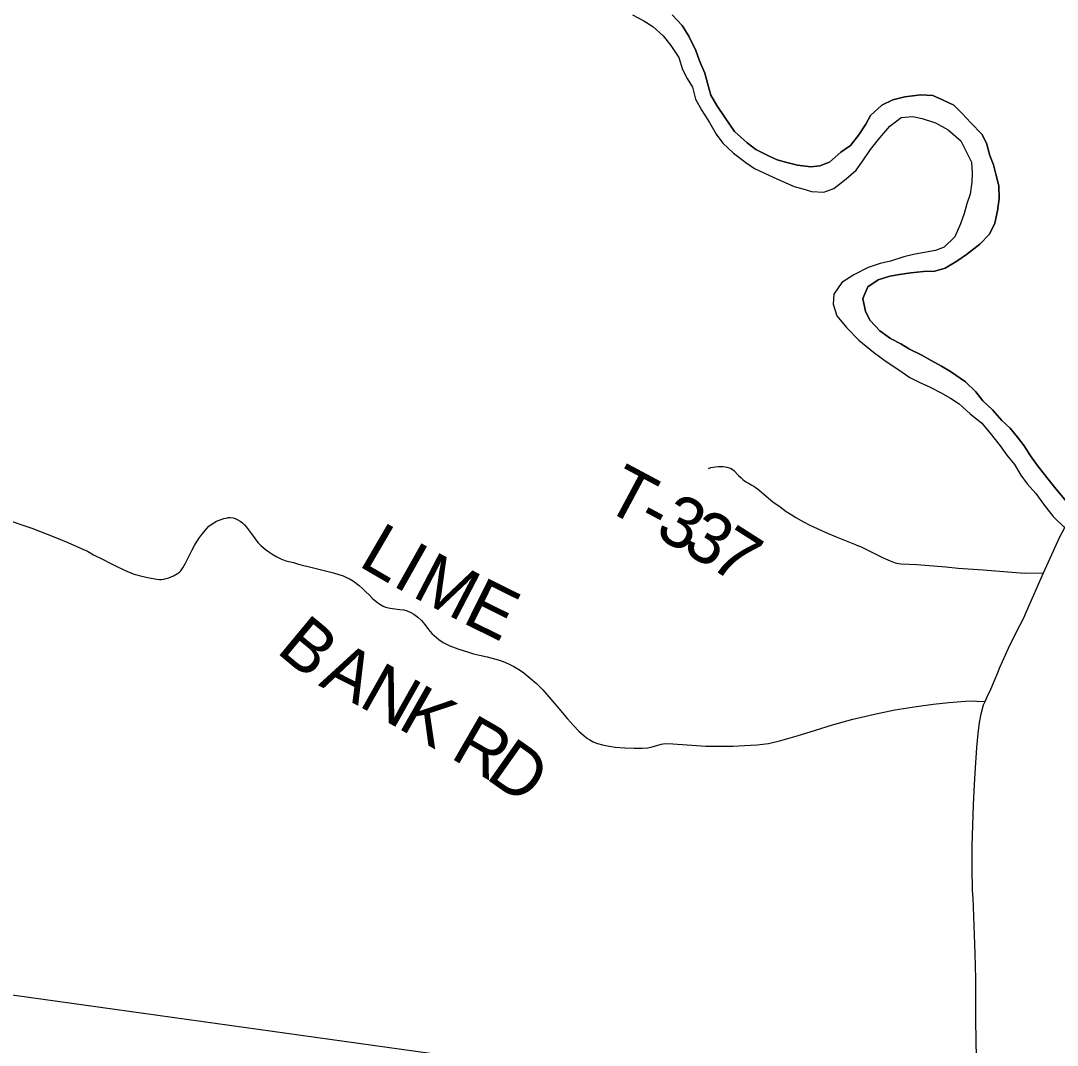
# Model space of a CAD drawing. Extents: x 0 to 34, y 0 to 22.
# Drawn here: x 6.535 to 7.688, y 17.181 to 18.32 of the extents above; entities that cross this region are included whole.
import ezdxf

# ---------------------------------------------------------------- set-up
doc = ezdxf.new("R2010")
doc.units = 0
for name, color, linetype in [('GM_X_County_Road', 7, 'Continuous'), ('GM_X_County_Road_Text', 7, 'Continuous'), ('GM_X_Major_River', 7, 'Continuous'), ('GM_X_Township_Road', 7, 'Continuous'), ('GM_X_Township_Road_Text', 7, 'Continuous'), ('SH_Text', 7, 'Continuous')]:
    doc.layers.add(name, color=color, linetype=linetype)

msp = doc.modelspace()

# ---------------------------------------------------------------- linework, layer by layer
at = {"layer": 'GM_X_County_Road'}
for points in [[(7.6778, 17.7185), (7.6905, 17.7463), (7.7139, 17.7898), (7.7207, 17.8036), (7.7258, 17.8149), (7.7303, 17.8264), (7.7343, 17.8381), (7.7388, 17.8529), (7.7434, 17.8694), (7.7504, 17.8946)], [(6.5182, 17.7655), (6.5469, 17.7559), (6.5725, 17.746), (6.587, 17.7401), (6.6011, 17.7339), (6.6087, 17.7303), (6.6156, 17.7265), (6.6262, 17.7212), (6.6334, 17.7173), (6.6393, 17.7144), (6.65, 17.7094), (6.6597, 17.7054), (6.6649, 17.7037), (6.6754, 17.701), (6.6818, 17.6999), (6.6861, 17.6993), (6.6889, 17.6991), (6.691, 17.6991), (6.6937, 17.6994), (6.6965, 17.7), (6.6993, 17.7008), (6.702, 17.7018), (6.7045, 17.7029), (6.7091, 17.7055), (6.7112, 17.7071), (6.7127, 17.7085), (6.715, 17.7118), (6.718, 17.7172), (6.7248, 17.7313), (6.7277, 17.7368), (6.7326, 17.7444), (6.7359, 17.7488), (6.7439, 17.7583), (6.7464, 17.7602), (6.7493, 17.7621), (6.7522, 17.7637), (6.7552, 17.7649), (6.7575, 17.7656), (6.7605, 17.7667), (6.7631, 17.7673), (6.7655, 17.7677), (6.7676, 17.7679), (6.7707, 17.7674), (6.7732, 17.7666), (6.7759, 17.7654), (6.7787, 17.7639), (6.7812, 17.7619), (6.7835, 17.7597), (6.7856, 17.7573), (6.7912, 17.7498), (6.7954, 17.744), (6.7984, 17.7401), (6.8018, 17.7366), (6.8064, 17.7326), (6.8107, 17.7296), (6.8151, 17.7267), (6.8195, 17.724), (6.824, 17.7218), (6.8296, 17.7198), (6.8378, 17.7177), (6.8435, 17.716), (6.849, 17.7145), (6.8544, 17.7132), (6.8602, 17.7119), (6.8825, 17.7062), (6.8931, 17.703), (6.8956, 17.702), (6.9011, 17.6994), (6.9046, 17.697), (6.9111, 17.6921), (6.9152, 17.6884), (6.9181, 17.6856), (6.9225, 17.6814), (6.926, 17.6779), (6.9299, 17.6743), (6.9339, 17.6715), (6.9377, 17.6693), (6.9402, 17.6682), (6.9454, 17.667), (6.9507, 17.6662), (6.9562, 17.6656), (6.9607, 17.665), (6.9645, 17.6639), (6.9686, 17.6623), (6.9719, 17.6603), (6.9764, 17.657), (6.9804, 17.6532), (6.9839, 17.6489), (6.9882, 17.6432), (6.992, 17.6387), (6.9996, 17.6322), (7.0045, 17.6288), (7.0119, 17.6253), (7.0207, 17.6219), (7.0326, 17.6182), (7.0383, 17.6164), (7.0449, 17.6149), (7.0536, 17.6129), (7.0655, 17.6095), (7.0713, 17.6076), (7.077, 17.6052), (7.0832, 17.6021), (7.0895, 17.5983), (7.0941, 17.595), (7.1014, 17.5893), (7.1082, 17.5833), (7.1154, 17.5762), (7.1332, 17.5553), (7.1427, 17.544), (7.1495, 17.5364), (7.1554, 17.5303), (7.1612, 17.5251), (7.1649, 17.5222), (7.1675, 17.5207), (7.1712, 17.5185), (7.1762, 17.5165), (7.1819, 17.515), (7.1874, 17.5139), (7.1957, 17.5125), (7.2065, 17.5116), (7.217, 17.5112), (7.2257, 17.5113), (7.232, 17.5118), (7.237, 17.5127), (7.2408, 17.5138), (7.2448, 17.5151), (7.247, 17.5157), (7.2491, 17.5162), (7.2515, 17.5164), (7.2601, 17.5162), (7.2759, 17.5151), (7.2968, 17.5136), (7.3123, 17.5134), (7.327, 17.5136), (7.3398, 17.5142), (7.3465, 17.5145), (7.3538, 17.515), (7.3663, 17.5165), (7.3803, 17.52), (7.3984, 17.5251), (7.4186, 17.5313), (7.4376, 17.5373), (7.4601, 17.5435), (7.4842, 17.5492), (7.507, 17.5538), (7.531, 17.5576), (7.5494, 17.5603), (7.5671, 17.5621), (7.5857, 17.5636), (7.5951, 17.5638), (7.5982, 17.5637), (7.6073, 17.5633)], [(7.6073, 17.5633), (7.6095, 17.5685), (7.6136, 17.5771), (7.6218, 17.5964), (7.6233, 17.6003), (7.6334, 17.6224), (7.6417, 17.6394), (7.6504, 17.6563), (7.6535, 17.6632), (7.6724, 17.7063), (7.6778, 17.7185)], [(7.5978, 17.1626), (7.5975, 17.191), (7.5971, 17.2049), (7.5969, 17.2385), (7.5969, 17.2549), (7.5964, 17.283), (7.5943, 17.3348), (7.5939, 17.3447), (7.5934, 17.3532), (7.5928, 17.3779), (7.5931, 17.4029), (7.5944, 17.4484), (7.5957, 17.4709), (7.5963, 17.4837), (7.5982, 17.5122), (7.5996, 17.5277), (7.6013, 17.54), (7.6031, 17.5497), (7.6056, 17.5595), (7.6073, 17.5633)]]:
    msp.add_lwpolyline(points, dxfattribs=at)
at = {"layer": 'GM_X_Major_River'}
for p, q in [((7.2152, 18.3269), (7.2277, 18.3202)), ((7.2702, 18.3149), (7.2591, 18.3269)), ((7.2277, 18.3202), (7.2376, 18.3139)), ((7.2376, 18.3139), (7.2494, 18.3037)), ((7.2778, 18.3032), (7.2702, 18.3149)), ((7.2494, 18.3037), (7.2579, 18.2928)), ((7.2855, 18.2874), (7.2778, 18.3032)), ((7.2579, 18.2928), (7.2667, 18.2796)), ((7.2667, 18.2796), (7.2706, 18.266)), ((7.2898, 18.2757), (7.2855, 18.2874)), ((7.2706, 18.266), (7.276, 18.2562)), ((7.2956, 18.2621), (7.2898, 18.2757)), ((7.276, 18.2562), (7.2817, 18.2464)), ((7.2987, 18.2508), (7.2956, 18.2621)), ((7.2817, 18.2464), (7.2852, 18.2332)), ((7.3022, 18.2375), (7.2987, 18.2508)), ((7.2852, 18.2332), (7.2922, 18.2204)), ((7.3091, 18.2262), (7.3022, 18.2375)), ((7.5047, 18.2325), (7.4923, 18.2264)), ((7.5179, 18.2357), (7.5047, 18.2325)), ((7.5357, 18.2378), (7.5179, 18.2357)), ((7.5493, 18.2371), (7.5357, 18.2378)), ((7.56, 18.2323), (7.5493, 18.2371)), ((7.5725, 18.2263), (7.56, 18.2323)), ((7.2922, 18.2204), (7.3006, 18.2072)), ((7.3183, 18.2123), (7.3091, 18.2262)), ((7.4923, 18.2264), (7.4799, 18.2149)), ((7.582, 18.217), (7.5725, 18.2263)), ((7.3287, 18.1972), (7.3183, 18.2123)), ((7.4799, 18.2149), (7.4747, 18.2054)), ((7.5012, 18.203), (7.514, 18.2129)), ((7.514, 18.2129), (7.5268, 18.2138)), ((7.5268, 18.2138), (7.5374, 18.2116)), ((7.5374, 18.2116), (7.5522, 18.2068)), ((7.5916, 18.2068), (7.582, 18.217)), ((7.3006, 18.2072), (7.3083, 18.194)), ((7.3428, 18.1845), (7.3287, 18.1972)), ((7.4747, 18.2054), (7.4668, 18.1935)), ((7.4903, 18.19), (7.5012, 18.203)), ((7.5522, 18.2068), (7.5663, 18.199)), ((7.5663, 18.199), (7.5804, 18.1866)), ((7.6038, 18.194), (7.5916, 18.2068)), ((7.3083, 18.194), (7.3156, 18.1842)), ((7.3523, 18.1773), (7.3428, 18.1845)), ((7.4668, 18.1935), (7.4575, 18.1817)), ((7.4798, 18.177), (7.4903, 18.19)), ((7.5804, 18.1866), (7.5923, 18.1632)), ((7.6088, 18.1842), (7.6038, 18.194)), ((7.6127, 18.1706), (7.6088, 18.1842)), ((7.3156, 18.1842), (7.3274, 18.173)), ((7.3274, 18.173), (7.3411, 18.1625)), ((7.3664, 18.1699), (7.3523, 18.1773)), ((7.447, 18.174), (7.4342, 18.1629)), ((7.4575, 18.1817), (7.447, 18.174)), ((7.4713, 18.1644), (7.4798, 18.177)), ((7.3411, 18.1625), (7.351, 18.1561)), ((7.3759, 18.1658), (7.3664, 18.1699)), ((7.3869, 18.1625), (7.3759, 18.1658)), ((7.3986, 18.1596), (7.3869, 18.1625)), ((7.4342, 18.1629), (7.4236, 18.1591)), ((7.4638, 18.1541), (7.4713, 18.1644)), ((7.5923, 18.1632), (7.5928, 18.1507)), ((7.6166, 18.1601), (7.6127, 18.1706)), ((7.351, 18.1561), (7.3715, 18.1464)), ((7.4134, 18.1578), (7.3986, 18.1596)), ((7.4236, 18.1591), (7.4134, 18.1578)), ((7.4529, 18.1445), (7.4638, 18.1541)), ((7.5928, 18.1507), (7.5925, 18.1409)), ((7.6193, 18.1498), (7.6166, 18.1601)), ((7.6225, 18.1366), (7.6193, 18.1498)), ((7.3715, 18.1464), (7.3856, 18.1401)), ((7.3856, 18.1401), (7.3951, 18.1361)), ((7.439, 18.1338), (7.4529, 18.1445)), ((7.5925, 18.1409), (7.5908, 18.1276)), ((7.3951, 18.1361), (7.4045, 18.1335)), ((7.4045, 18.1335), (7.4144, 18.1305)), ((7.4144, 18.1305), (7.428, 18.1295)), ((7.428, 18.1295), (7.439, 18.1338)), ((7.5908, 18.1276), (7.5871, 18.1166)), ((7.623, 18.1226), (7.6225, 18.1366)), ((7.5871, 18.1166), (7.5841, 18.1059)), ((7.6212, 18.1089), (7.623, 18.1226)), ((7.5841, 18.1059), (7.5801, 18.0945)), ((7.6183, 18.0953), (7.6212, 18.1089)), ((7.5801, 18.0945), (7.5738, 18.0801)), ((7.6123, 18.0831), (7.6183, 18.0953)), ((7.6015, 18.072), (7.6123, 18.0831)), ((7.5738, 18.0801), (7.5618, 18.0686)), ((7.5868, 18.0605), (7.6015, 18.072)), ((7.5168, 18.0576), (7.5021, 18.0529)), ((7.5278, 18.0603), (7.5168, 18.0576)), ((7.5418, 18.0631), (7.5278, 18.0603)), ((7.552, 18.0647), (7.5418, 18.0631)), ((7.5618, 18.0686), (7.552, 18.0647)), ((7.5759, 18.0528), (7.5868, 18.0605)), ((7.4908, 18.0505), (7.4772, 18.0459)), ((7.5021, 18.0529), (7.4908, 18.0505)), ((7.5631, 18.0451), (7.5759, 18.0528)), ((7.4614, 18.0378), (7.4478, 18.0293)), ((7.4772, 18.0459), (7.4614, 18.0378)), ((7.4883, 18.0323), (7.5015, 18.0362)), ((7.5015, 18.0362), (7.5121, 18.0382)), ((7.5121, 18.0382), (7.5246, 18.0398)), ((7.5246, 18.0398), (7.5389, 18.0415)), ((7.5389, 18.0415), (7.5514, 18.042)), ((7.5514, 18.042), (7.5631, 18.0451)), ((7.4478, 18.0293), (7.4389, 18.0163)), ((7.4714, 18.0113), (7.477, 18.0243)), ((7.477, 18.0243), (7.4883, 18.0323)), ((7.4389, 18.0163), (7.4382, 18.0053)), ((7.4742, 17.9969), (7.4714, 18.0113)), ((7.4382, 18.0053), (7.4425, 17.9921)), ((7.4425, 17.9921), (7.4532, 17.9793)), ((7.4796, 17.9871), (7.4742, 17.9969)), ((7.4532, 17.9793), (7.4669, 17.965)), ((7.4903, 17.9755), (7.4796, 17.9871)), ((7.5021, 17.9669), (7.4903, 17.9755)), ((7.5135, 17.9609), (7.5021, 17.9669)), ((7.4669, 17.965), (7.4833, 17.9519)), ((7.5234, 17.955), (7.5135, 17.9609)), ((7.5363, 17.9486), (7.5234, 17.955)), ((7.4833, 17.9519), (7.4974, 17.9415)), ((7.5473, 17.9423), (7.5363, 17.9486)), ((7.5588, 17.9363), (7.5473, 17.9423)), ((7.4974, 17.9415), (7.5103, 17.9329)), ((7.5103, 17.9329), (7.5237, 17.9235)), ((7.569, 17.9304), (7.5588, 17.9363)), ((7.5237, 17.9235), (7.5339, 17.9183)), ((7.5854, 17.9188), (7.569, 17.9304)), ((7.5339, 17.9183), (7.5461, 17.9127)), ((7.5461, 17.9127), (7.5579, 17.9068)), ((7.5972, 17.9075), (7.5854, 17.9188)), ((7.6049, 17.8977), (7.5972, 17.9075)), ((7.5579, 17.9068), (7.5689, 17.9004)), ((7.5689, 17.9004), (7.5784, 17.8941)), ((7.6156, 17.8876), (7.6049, 17.8977)), ((7.5784, 17.8941), (7.5906, 17.8832)), ((7.6259, 17.8759), (7.6156, 17.8876)), ((7.5906, 17.8832), (7.6032, 17.8731)), ((7.6032, 17.8731), (7.6131, 17.8618)), ((7.6354, 17.8673), (7.6259, 17.8759)), ((7.6131, 17.8618), (7.6242, 17.8475)), ((7.6434, 17.8571), (7.6354, 17.8673)), ((7.6507, 17.8474), (7.6434, 17.8571)), ((7.6242, 17.8475), (7.6315, 17.8373)), ((7.658, 17.8364), (7.6507, 17.8474)), ((7.6315, 17.8373), (7.6399, 17.8268)), ((7.6399, 17.8268), (7.6472, 17.8151)), ((7.6653, 17.8259), (7.658, 17.8364)), ((7.676, 17.8123), (7.6653, 17.8259)), ((7.6472, 17.8151), (7.6541, 17.8053)), ((7.6541, 17.8053), (7.6637, 17.7944)), ((7.6848, 17.8011), (7.676, 17.8123)), ((7.6637, 17.7944), (7.6736, 17.7813)), ((7.6974, 17.786), (7.6848, 17.8011)), ((7.6736, 17.7813), (7.6832, 17.7688)), ((7.6832, 17.7688), (7.6962, 17.7564))]:
    msp.add_line(p, q, dxfattribs=at)
for points in [[(7.2152, 18.3269), (7.2277, 18.3202), (7.2376, 18.3139), (7.2494, 18.3037), (7.2579, 18.2928), (7.2667, 18.2796), (7.2706, 18.266), (7.276, 18.2562), (7.2817, 18.2464), (7.2852, 18.2332), (7.2922, 18.2204), (7.3006, 18.2072), (7.3083, 18.194), (7.3156, 18.1842), (7.3274, 18.173), (7.3411, 18.1625), (7.351, 18.1561), (7.3715, 18.1464), (7.3856, 18.1401), (7.3951, 18.1361), (7.4045, 18.1335), (7.4144, 18.1305), (7.428, 18.1295), (7.439, 18.1338), (7.4529, 18.1445), (7.4638, 18.1541), (7.4713, 18.1644), (7.4798, 18.177), (7.4903, 18.19), (7.5012, 18.203), (7.514, 18.2129), (7.5268, 18.2138)], [(7.2591, 18.3269), (7.2702, 18.3149), (7.2778, 18.3032), (7.2855, 18.2874), (7.2898, 18.2757), (7.2956, 18.2621), (7.2987, 18.2508), (7.3022, 18.2375), (7.3091, 18.2262), (7.3183, 18.2123), (7.3287, 18.1972), (7.3428, 18.1845), (7.3523, 18.1773), (7.3664, 18.1699), (7.3759, 18.1658), (7.3869, 18.1625), (7.3986, 18.1596), (7.4134, 18.1578), (7.4236, 18.1591), (7.4342, 18.1629), (7.447, 18.174), (7.4575, 18.1817), (7.4668, 18.1935), (7.4747, 18.2054), (7.4799, 18.2149), (7.4923, 18.2264), (7.5047, 18.2325), (7.5179, 18.2357), (7.5357, 18.2378), (7.5493, 18.2371)], [(7.5493, 18.2371), (7.56, 18.2323), (7.5725, 18.2263), (7.582, 18.217), (7.5916, 18.2068), (7.6038, 18.194), (7.6088, 18.1842), (7.6127, 18.1706), (7.6166, 18.1601), (7.6193, 18.1498), (7.6225, 18.1366), (7.623, 18.1226), (7.6212, 18.1089), (7.6183, 18.0953), (7.6123, 18.0831), (7.6015, 18.072), (7.5868, 18.0605), (7.5759, 18.0528), (7.5631, 18.0451), (7.5514, 18.042), (7.5389, 18.0415), (7.5246, 18.0398), (7.5121, 18.0382), (7.5015, 18.0362), (7.4883, 18.0323), (7.477, 18.0243), (7.4714, 18.0113), (7.4742, 17.9969), (7.4796, 17.9871), (7.4903, 17.9755), (7.5021, 17.9669), (7.5135, 17.9609), (7.5234, 17.955), (7.5363, 17.9486), (7.5473, 17.9423), (7.5588, 17.9363), (7.569, 17.9304), (7.5854, 17.9188), (7.5972, 17.9075), (7.6049, 17.8977), (7.6156, 17.8876), (7.6259, 17.8759), (7.6354, 17.8673), (7.6434, 17.8571), (7.6507, 17.8474), (7.658, 17.8364), (7.6653, 17.8259), (7.676, 17.8123), (7.6848, 17.8011), (7.6974, 17.786)], [(7.5268, 18.2138), (7.5374, 18.2116), (7.5522, 18.2068), (7.5663, 18.199), (7.5804, 18.1866), (7.5923, 18.1632), (7.5928, 18.1507), (7.5925, 18.1409), (7.5908, 18.1276), (7.5871, 18.1166), (7.5841, 18.1059), (7.5801, 18.0945), (7.5738, 18.0801), (7.5618, 18.0686), (7.552, 18.0647), (7.5418, 18.0631), (7.5278, 18.0603), (7.5168, 18.0576), (7.5021, 18.0529), (7.4908, 18.0505), (7.4772, 18.0459), (7.4614, 18.0378), (7.4478, 18.0293), (7.4389, 18.0163), (7.4382, 18.0053), (7.4425, 17.9921), (7.4532, 17.9793), (7.4669, 17.965), (7.4833, 17.9519), (7.4974, 17.9415), (7.5103, 17.9329), (7.5237, 17.9235), (7.5339, 17.9183), (7.5461, 17.9127), (7.5579, 17.9068), (7.5689, 17.9004), (7.5784, 17.8941), (7.5906, 17.8832), (7.6032, 17.8731), (7.6131, 17.8618), (7.6242, 17.8475), (7.6315, 17.8373), (7.6399, 17.8268), (7.6472, 17.8151), (7.6541, 17.8053), (7.6637, 17.7944), (7.6736, 17.7813), (7.6832, 17.7688), (7.6962, 17.7564)]]:
    msp.add_lwpolyline(points, dxfattribs=at)
at = {"layer": 'GM_X_Township_Road'}
msp.add_lwpolyline([(7.2996, 17.8225), (7.3022, 17.8233), (7.3048, 17.8239), (7.3074, 17.8244), (7.3106, 17.8246), (7.3134, 17.8246), (7.3159, 17.8245), (7.3181, 17.8242), (7.3201, 17.8238), (7.3227, 17.823), (7.3247, 17.8222), (7.3263, 17.8212), (7.3278, 17.8201), (7.333, 17.8145), (7.336, 17.8118), (7.3378, 17.81), (7.3397, 17.8086), (7.342, 17.8072), (7.3443, 17.8061), (7.3461, 17.805), (7.348, 17.8038), (7.3499, 17.8026), (7.3518, 17.8014), (7.3537, 17.8), (7.3559, 17.7982), (7.3712, 17.7853), (7.3792, 17.7798), (7.386, 17.7745), (7.3916, 17.7712), (7.3967, 17.7679), (7.4055, 17.763), (7.4125, 17.7594), (7.4293, 17.7515), (7.4417, 17.7465), (7.4621, 17.7382), (7.4654, 17.7369), (7.4687, 17.7355), (7.4732, 17.7334), (7.4941, 17.7231), (7.5017, 17.7195), (7.5036, 17.7188), (7.5073, 17.7176), (7.5093, 17.7172), (7.5113, 17.7168), (7.5139, 17.7165), (7.5313, 17.7156), (7.5638, 17.713), (7.5773, 17.7116), (7.6051, 17.7095), (7.6513, 17.7061), (7.6724, 17.7063)], dxfattribs=at)
at = {"layer": 'SH_Text'}
msp.add_lwpolyline([(5.3474, 17.401), (9.2222, 16.4501), (9.2222, 16.8603)], close=True, dxfattribs=at)

# ---------------------------------------------------------------- texts
at = {"layer": 'GM_X_County_Road_Text'}
for s, rotation, p in [('L', 329.7602, (6.9088, 17.7149)), ('I', 330.6413, (6.9463, 17.6931)), ('M', 332.5252, (6.9684, 17.6807)), ('E', 333.6546, (7.0242, 17.6517)), ('B', 320.3204, (6.8176, 17.6187)), ('A', 333.0064, (6.8649, 17.5814)), ('N', 330.6089, (6.9089, 17.559)), ('K', 330.3708, (6.9524, 17.5345)), ('R', 329.9768, (7.011, 17.5012)), ('D', 324.7579, (7.0503, 17.4786))]:
    msp.add_text(s, height=0.0568, rotation=rotation, dxfattribs=at).set_placement(p)
at = {"layer": 'GM_X_Township_Road_Text'}
for s, rotation, p in [('T', 331.8363, (7.1805, 17.7788)), ('3', 331.3119, (7.2384, 17.7477)), ('-', 331.7172, (7.2179, 17.7587)), ('3', 329.8207, (7.2687, 17.7311)), ('7', 327.4618, (7.2984, 17.7139))]:
    msp.add_text(s, height=0.0568, rotation=rotation, dxfattribs=at).set_placement(p)

doc.saveas('drawing.dxf')
